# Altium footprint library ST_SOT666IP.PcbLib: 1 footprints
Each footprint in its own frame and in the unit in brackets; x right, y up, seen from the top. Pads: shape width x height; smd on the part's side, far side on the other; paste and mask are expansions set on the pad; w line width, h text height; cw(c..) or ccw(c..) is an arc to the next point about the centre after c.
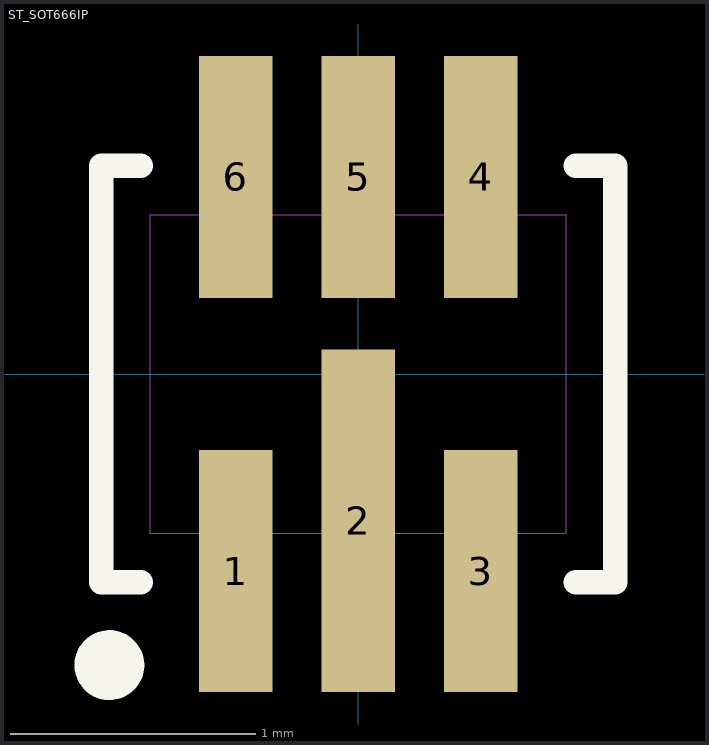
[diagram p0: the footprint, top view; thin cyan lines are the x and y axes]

## ST_SOT666IP [mm] "ST_SOT666IP"
pads (6):
  rect 0.3x0.99 smd mask+0.025: 1(-0.5,-0.805) 3(0.5,-0.805) 4(0.5,0.805) 5(0,0.805) 6(-0.5,0.805)
  rect 0.3x1.4 smd mask+0.025: 2(0,-0.6)
Top Overlay:
  circle w0.15: c-1.017,-1.189 r0.068
  lines w0.1: -0.889,-0.85 -1.05,-0.85 -1.05,0.85 -0.889,0.85 ; 0.889,-0.85 1.05,-0.85 1.05,0.85 0.889,0.85
Mechanical 5:
  text "1" at -0.61,-1.905 h0.3
  text "2" at -0.13,-1.885 h0.3
  text "3" at 0.39,-1.905 h0.3
  text "4" at 0.39,1.605 h0.3
  text "5" at -0.11,1.605 h0.3
  text "6" at -0.61,1.605 h0.3
Mechanical 6:
  lines w0: -0.85,-0.65 0.85,-0.65 0.85,0.65 -0.85,0.65 -0.85,-0.65
3D body: height 0.6, standoff 0, extent -0.85,-0.65 0.85,0.65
